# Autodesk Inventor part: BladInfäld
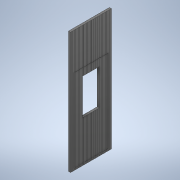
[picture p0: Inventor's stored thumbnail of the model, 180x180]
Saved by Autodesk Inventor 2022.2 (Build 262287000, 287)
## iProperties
Created: 2019-06
Part Number: BladInfäld
Material: UHMW, Black
Document SubType Name: Modeling
Designer: cl
Density: 0.94 g/cm^3
Appearance: Smooth - Black
Author: cl
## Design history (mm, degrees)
sketch "Sketch4"
  geometry: L1 (0, 0)-(0, -35); L2 (0, -35)-(1.4, -36.4); L3 (1.4, -36.4)-(1.4, -96.4); L4 (1.4, -96.4)-(0, -97.8); L5 (0, 0)-(-23.6, 0); L6 (0, -97.8)-(-23.6, -97.8); L7 (-23.6, -97.8)-(-23.6, 0); L8 (-47.2, 0)-(-23.6, 0); L9 (-47.2, 0)-(-47.2, -35); L10 (-47.2, -35)-(-48.6, -36.4); L11 (-48.6, -36.4)-(-48.6, -96.4); L12 (-48.6, -96.4)-(-47.2, -97.8); L13 (-47.2, -97.8)-(-23.6, -97.8); 1 further point
  constraints: 26 end point, 5 symmetric about line, 3 vertical, 2 horizontal, 1 coincident
  dimensions: "d41" = 35 distance of L1.start L1.end; "d43" = 45 deg angle of L2 L1; "d44" = 60 distance of L2.end L3.end; "d45" = 45 deg angle of L3 L4; "d46" = 1.4 distance between parallel lines of L1 L3; "d47" = 1.4 horizontal distance of L3.end L4.end (derived); "d48" = 23.6 distance of L1.start L5.end
extrude "Extrusion2" new body sketch "Sketch4" distance "d49" = 2921 (derived); taper "d50" = 0 deg
sketch "Sketch5"
  geometry: L1 (-48.6, -96.4)-(-47.2, -97.8) reference; L2 (-47.2, -97.8)-(-47.2, -127.8); L3 (-47.2, -97.8)-(-17.2, -97.8); L4 (-47.2, -127.8)-(-48.6, -129.2); L5 (-48.6, -129.2)-(-48.6, -189.2); L6 (-47.2, -97.8)-(-23.6, -97.8); L7 (-47.2, -97.8)-(0, -97.8) reference; L8 (-23.6, -97.8)-(-23.6, -190.6); L9 (-48.6, -189.2)-(-47.2, -190.6); L10 (-47.2, -190.6)-(-23.6, -190.6); L11 (0, -97.8)-(-30, -97.8); L12 (0, -97.8)-(0, -127.8); L13 (0, -127.8)-(1.4, -129.2); L14 (1.4, -129.2)-(1.4, -189.2); L15 (0, -190.6)-(-23.6, -190.6); L16 (1.4, -189.2)-(0, -190.6); 1 further point
  constraints: 28 end point, 5 symmetric about line, 2 horizontal, 2 perpendicular, 2 vertical, 1 midpoint, 1 parallel
  dimensions: "d51" = 30 distance of L1.end L2.end; "d52" = 90 deg angle of L2 L3 (derived); "d54" = 1.4 distance between parallel lines of L2 L5; "d55" = 23.6 distance of L1.end L6.end; "d56" = 45 deg angle of L9 L5; "d57" = 1.4 distance from line of L5 L9.end; "d60" = 60 distance of L4.end L5.end
extrude "Extrusion3" join sketch "Sketch5" distance "d58" = 2921 (derived); taper "d59" = 0 deg
pattern_linear "Rectangular Pattern1" dims "d61" = 85.33405 (derived), "d63" = 92.8
sketch "Sketch7"
  geometry: L1 (-47.2, -189.233)-(0, -189.233); L2 (0, -189.233)-(0, -983.5); L3 (0, -983.5)-(-47.2, -983.5); L4 (-47.2, -983.5)-(-47.2, -189.233); L5 (0, 0)-(-47.2, 0) reference; L6 (-47.2, -97.8)-(-47.2, -127.8) reference; L7 (-47.2, -127.8)-(-48.6, -129.2) reference; L8 (-48.6, -129.2)-(-48.6, -189.2) reference; L9 (-48.6, -189.2)-(-47.2, -190.6) reference; L10 (-47.2, -190.6)-(-47.2, -220.6) reference; L11 (-47.2, -220.6)-(-48.6, -222) reference; L12 (-48.6, -222)-(-48.6, -282) reference; L13 (-48.6, -282)-(-47.2, -283.4) reference; L14 (-47.2, -283.4)-(-47.2, -313.4) reference; L15 (-47.2, -313.4)-(-48.6, -314.8) reference; L16 (-48.6, -314.8)-(-48.6, -374.8) reference; L17 (-48.6, -374.8)-(-47.2, -376.2) reference; L18 (0, -376.2)-(1.4, -374.8) reference; L19 (1.4, -374.8)-(1.4, -314.8) reference; L20 (1.4, -314.8)-(0, -313.4) reference; L21 (0, -313.4)-(0, -283.4) reference; L22 (0, -283.4)-(1.4, -282) reference; L23 (1.4, -282)-(1.4, -222) reference; L24 (1.4, -222)-(0, -220.6) reference; L25 (0, -220.6)-(0, -190.6) reference; L26 (0, -190.6)-(1.4, -189.2) reference; L27 (1.4, -189.2)-(1.4, -129.2) reference; L28 (1.4, -129.2)-(0, -127.8) reference; L29 (0, -127.8)-(0, -97.8) reference; L30 (-47.2, -35)-(-48.6, -36.4) reference; L31 (-48.6, -36.4)-(-48.6, -96.4) reference; L32 (-48.6, -96.4)-(-47.2, -97.8) reference; L33 (0, -97.8)-(1.4, -96.4) reference; L34 (1.4, -96.4)-(1.4, -36.4) reference; L35 (1.4, -36.4)-(0, -35) reference; L36 (0, -35)-(0, 0) reference; L37 (0, 0)-(-47.2, 0) reference; L38 (-47.2, 0)-(-47.2, -35) reference; L39 (-47.2, -376.2)-(-47.2, -406.2) reference; L40 (-47.2, -406.2)-(-48.6, -407.6) reference; L41 (-48.6, -407.6)-(-48.6, -467.6) reference; L42 (-48.6, -467.6)-(-47.2, -469) reference; L43 (-47.2, -469)-(-47.2, -499) reference; L44 (-47.2, -499)-(-48.6, -500.4) reference; L45 (-48.6, -500.4)-(-48.6, -560.4) reference; L46 (-48.6, -560.4)-(-47.2, -561.8) reference; L47 (0, -561.8)-(1.4, -560.4) reference; L48 (1.4, -560.4)-(1.4, -500.4) reference; L49 (1.4, -500.4)-(0, -499) reference; L50 (0, -499)-(0, -469) reference; L51 (0, -469)-(1.4, -467.6) reference; L52 (1.4, -467.6)-(1.4, -407.6) reference; L53 (1.4, -407.6)-(0, -406.2) reference; L54 (0, -406.2)-(0, -376.2) reference; L55 (-47.2, -561.8)-(-47.2, -591.8) reference; L56 (-47.2, -591.8)-(-48.6, -593.2) reference; L57 (-48.6, -593.2)-(-48.6, -653.2) reference; L58 (-48.6, -653.2)-(-47.2, -654.6) reference; L59 (-47.2, -654.6)-(-47.2, -684.6) reference; L60 (-47.2, -684.6)-(-48.6, -686) reference; L61 (-48.6, -686)-(-48.6, -746) reference; L62 (-48.6, -746)-(-47.2, -747.4) reference; L63 (0, -747.4)-(1.4, -746) reference; L64 (1.4, -746)-(1.4, -686) reference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; 2 further points
  constraints: 8 end point, 2 parallel, 2 point on line, 1 horizontal, 1 perpendicular
  dimensions: "d67" = 983.5 distance between parallel lines of L5 L3 (derived); "d103" = 47.2 distance between parallel lines of L2 L4
extrude "Extrusion5" join sketch "Sketch7" distance "d68" = 2921 (derived); taper "d69" = 0 deg
sketch "Sketch10"
  geometry: L1 (195.35, 1862)-(595.35, 1862); L2 (595.35, 1862)-(595.35, 1000); L3 (595.35, 1000)-(195.35, 1000); L4 (195.35, 1000)-(195.35, 1862); L5 (395.35, 1000)-(395.35, 1862); L6 (195.35, 1000)-(595.35, 1000); L7 (595.35, 1000)-(595.35, 1862); L8 (595.35, 1862)-(195.35, 1862); L9 (195.35, 1862)-(195.35, 1000); L10 (395.35, 1862)-(395.35, 1000); 1 further point
  constraints: 20 end point, 4 midpoint, 4 parallel, 2 horizontal, 2 perpendicular, 1 collinear
  dimensions: "d82" = 862 distance of L1.end L2.end (derived); "d83" = 400 distance of L2.end L3.end (derived); "d86" = 491.75 distance from line of L5 point (-96.4, 0) (derived); "d92" = 1000 distance from line of point (-96.4, 0) L3 (derived); "d93" = 400 distance of L6.start L6.end (derived); "d94" = 862 distance of L6.end L7.end (derived); "d95" = 0.0001 distance between parallel lines of L3 L6 (derived)
extrude "Extrusion8" cut sketch "Sketch10" stored distance "d87" = 100; taper "d88" = 0 deg
sketch "Sketch13"
  geometry: L1 (-35, 0)-(-35, 2921) reference; L2 (711, 0)-(712.4, 0) reference; L3 (651, 0)-(711, 0) reference; L4 (649.6, 0)-(651, 0) reference; L5 (619.6, 0)-(649.6, 0) reference; L6 (618.2, 0)-(619.6, 0) reference; L7 (558.2, 0)-(618.2, 0) reference; L8 (556.8, 0)-(558.2, 0) reference; L9 (526.8, 0)-(556.8, 0) reference; L10 (525.4, 0)-(526.8, 0) reference; L11 (465.4, 0)-(525.4, 0) reference; L12 (464, 0)-(465.4, 0) reference; L13 (434, 0)-(464, 0) reference; L14 (432.6, 0)-(434, 0) reference; L15 (372.6, 0)-(432.6, 0) reference; L16 (371.2, 0)-(372.6, 0) reference; L17 (341.2, 0)-(371.2, 0) reference; L18 (339.8, 0)-(341.2, 0) reference; L19 (279.8, 0)-(339.8, 0) reference; L20 (278.4, 0)-(279.8, 0) reference; L21 (248.4, 0)-(278.4, 0) reference; L22 (247, 0)-(248.4, 0) reference; L23 (187, 0)-(247, 0) reference; L24 (185.6, 0)-(187, 0) reference; L25 (155.6, 0)-(185.6, 0) reference; L26 (154.2, 0)-(155.6, 0) reference; L27 (94.2, 0)-(154.2, 0) reference; L28 (92.8, 0)-(94.2, 0) reference; L29 (62.8, 0)-(92.8, 0) reference; L30 (61.4, 0)-(62.8, 0) reference; L31 (1.4, 0)-(61.4, 0) reference; L32 (0, 0)-(1.4, 0) reference; L33 (-35, 0)-(0, 0) reference; L34 (0, 0)-(-35, 0) reference; L35 (1.4, 0)-(0, 0) reference; L36 (61.4, 0)-(1.4, 0) reference; L37 (62.8, 0)-(61.4, 0) reference; L38 (92.8, 0)-(62.8, 0) reference; L39 (94.2, 0)-(92.8, 0) reference; L40 (154.2, 0)-(94.2, 0) reference; L41 (155.6, 0)-(154.2, 0) reference; L42 (185.6, 0)-(155.6, 0) reference; L43 (187, 0)-(185.6, 0) reference; L44 (247, 0)-(187, 0) reference; L45 (248.4, 0)-(247, 0) reference; L46 (278.4, 0)-(248.4, 0) reference; L47 (279.8, 0)-(278.4, 0) reference; L48 (339.8, 0)-(279.8, 0) reference; L49 (341.2, 0)-(339.8, 0) reference; L50 (371.2, 0)-(341.2, 0) reference; L51 (372.6, 0)-(371.2, 0) reference; L52 (432.6, 0)-(372.6, 0) reference; L53 (434, 0)-(432.6, 0) reference; L54 (464, 0)-(434, 0) reference; L55 (465.4, 0)-(464, 0) reference; L56 (525.4, 0)-(465.4, 0) reference; L57 (526.8, 0)-(525.4, 0) reference; L58 (556.8, 0)-(526.8, 0) reference; L59 (558.2, 0)-(556.8, 0) reference; L60 (618.2, 0)-(558.2, 0) reference; L61 (619.6, 0)-(618.2, 0) reference; L62 (649.6, 0)-(619.6, 0) reference; L63 (651, 0)-(649.6, 0) reference; L64 (711, 0)-(651, 0) reference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
  constraints: 16 end point, 4 parallel, 2 perpendicular, 1 horizontal, 3 other
  dimensions: "d96" = 1993 distance of L70.end L71.end; "d97" = 8.5 distance between parallel lines of L73 L77; "d98" = 82 distance between parallel lines of L68 L71; "d99" = 82 distance between parallel lines of L1 L73; "d100" = 49 distance between parallel lines of L46 L72
extrude "Extrusion10" cut sketch "Sketch13" stored distance "d101" = 100; taper "d102" = 0 deg
body "Solid2"
node "Projected Loop1"
node "Projected Loop4"
node "Projected Loop5"
other parameters: "d24" = 45 deg, "BladBredd" = 987.5, "AntalVeck" = 9.88685 (computed from BladBredd) [user parameter], "Fönsterhöjd" = 862, "Blad2" = 1012.5, "Blad3" = 0, "Blad4" = 0, "Blad5" = 1012.5, "Blad6" = 2025, "MGJ12Djup" = 0, "MGJ12Bredd" = 0, "MGJ2Djup" = 0, "MGJ2Bredd" = 5012.5, "MGJ56Djup" = 0, "MGJ56Bredd" = 0, "MGJ23Djup" = 48, "MGJ45Djup" = 48, "GarageRegel5" = 0, "GarageRegel6" = 0, "Styrrulle2Djup" = 0, "FönsterhöjdStyrning" = 862, "FönsterKarm" = 54, "AndraGlasraden" = 0, "BrösthöjdStyrning2" = 0.0001, "InfälldGångDörr" = 0, "Infälldstyr" = 1012.5
